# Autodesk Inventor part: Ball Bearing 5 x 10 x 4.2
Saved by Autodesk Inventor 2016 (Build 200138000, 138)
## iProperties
Created: 2016-01
Part Number: Ball Bearing 5 x 10 x 4.2
Material: Generic
Document SubType Name: Modeling
Designer: John
Density: 1 g/cm^3
Appearance: Default
Author: John
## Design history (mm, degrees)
feature "REVOLVE1"
body "Solid1"
